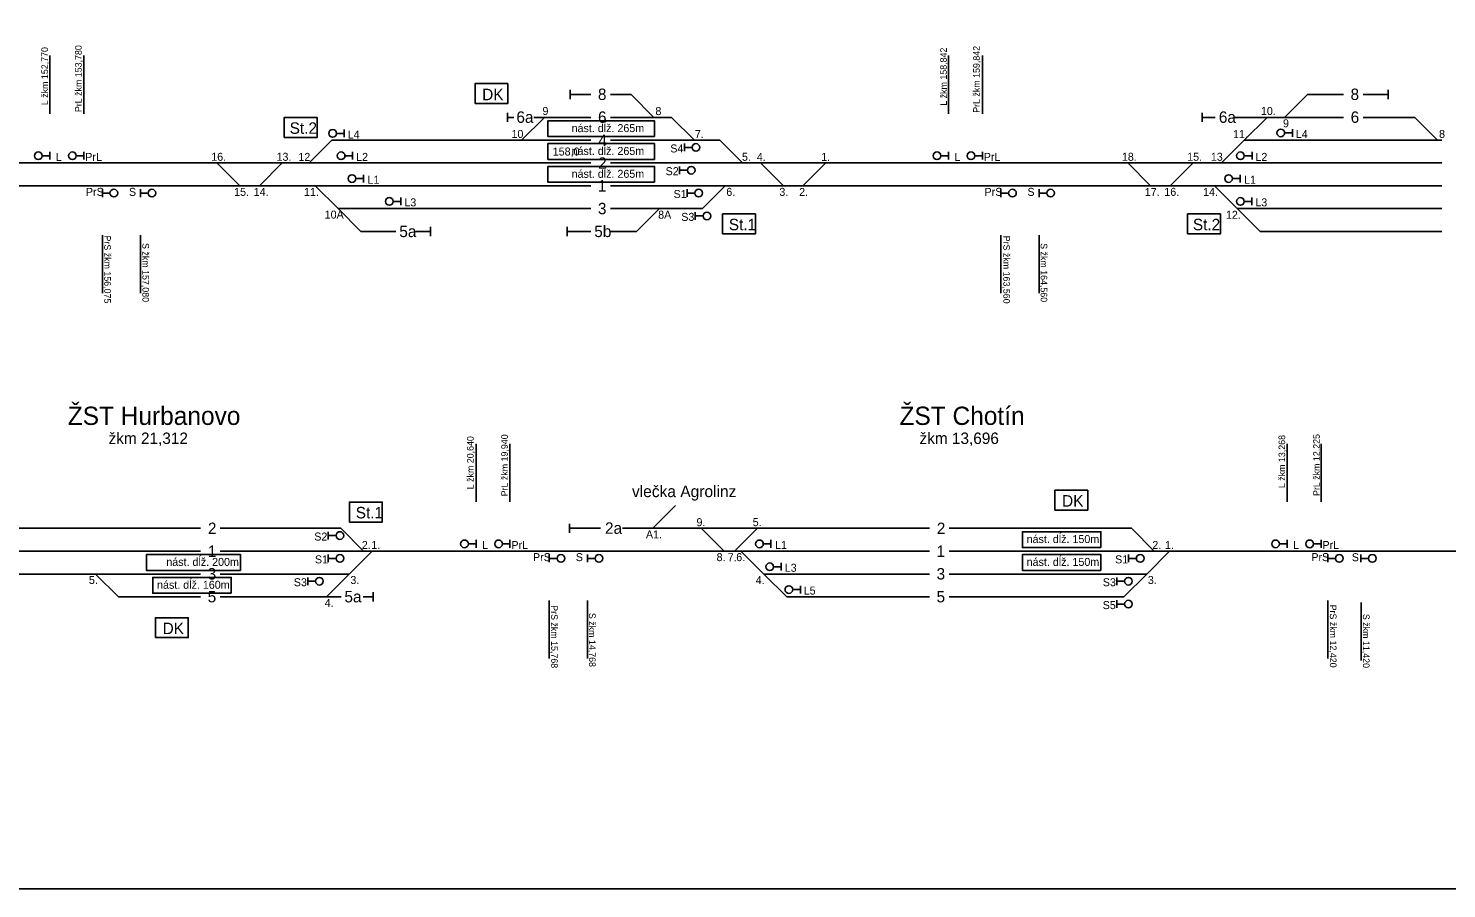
# Model space of a CAD drawing. Extents: x -119 to 851, y -238 to 59.
# Drawn here: x 119.9 to 243.9, y -238 to -162.7 of the extents above; entities that cross this region are included whole.
import ezdxf

# ---------------------------------------------------------------- set-up
doc = ezdxf.new("R2010")
doc.units = 0
for name, color, linetype in [('budova', 7, 'Continuous'), ('Level 2', 7, 'Continuous'), ('nastupistia', 7, 'Continuous'), ('netlač', 7, 'Continuous'), ('popisky navestidla', 7, 'Continuous'), ('popisky stanic a zastavok', 7, 'Continuous'), ('PU_navestidla', 7, 'Continuous'), ('PU_oznacenie navestidiel', 7, 'Continuous'), ('PU_stan_kolaje', 7, 'Continuous'), ('PU_vlecky', 7, 'Continuous'), ('schema_km1-0', 7, 'Continuous')]:
    doc.layers.add(name, color=color, linetype=linetype)

msp = doc.modelspace()

# ---------------------------------------------------------------- linework, layer by layer
at = {"layer": 'budova'}
for points in [[(158.96, -169.3), (161.82, -169.3), (161.82, -167.55), (158.96, -167.55)], [(142.27, -172.26), (145.14, -172.26), (145.14, -170.51), (142.27, -170.51)], [(180.61, -180.7), (183.48, -180.7), (183.48, -178.95), (180.61, -178.95)], [(221.27, -180.7), (224.14, -180.7), (224.14, -178.95), (221.27, -178.95)], [(209.67, -204.88), (212.54, -204.88), (212.54, -203.13), (209.67, -203.13)], [(147.97, -205.92), (150.84, -205.92), (150.84, -204.17), (147.97, -204.17)], [(131, -216.04), (133.87, -216.04), (133.87, -214.29), (131, -214.29)]]:
    msp.add_lwpolyline(points, close=True, dxfattribs=at)
at = {"layer": 'Level 2'}
for p, q in [((167.26, -168.9), (167.26, -168.1)), ((169.07, -168.5), (167.26, -168.5)), ((172.6, -168.5), (170.8, -168.5)), ((171.05, -168.5), (170.9, -168.5)), ((234.91, -168.5), (231.76, -168.5)), ((238.83, -168.5), (236.63, -168.5)), ((238.83, -168.9), (238.83, -168.1)), ((161.8, -170.9), (161.8, -170.1)), ((162.35, -170.5), (161.8, -170.5)), ((169.07, -170.5), (164.1, -170.5)), ((168.69, -170.5), (168.47, -170.5)), ((176.15, -170.5), (170.8, -170.5)), ((222.55, -170.9), (222.55, -170.1)), ((223.7, -170.5), (222.55, -170.5)), ((234.91, -170.5), (225.42, -170.5)), ((241.14, -170.5), (236.63, -170.5)), ((146.43, -172.49), (169.07, -172.49)), ((170.8, -172.49), (180.37, -172.49)), ((226.23, -172.49), (243.51, -172.49)), ((99.1, -174.49), (121.77, -174.49)), ((129.68, -174.49), (137.9, -174.49)), ((137.9, -174.49), (154.1, -174.49)), ((154.1, -174.49), (169.07, -174.49)), ((170.8, -174.49), (177.69, -174.49)), ((177.69, -174.49), (200.36, -174.49)), ((208.28, -174.49), (212.34, -174.49)), ((212.34, -174.49), (228.53, -174.49)), ((228.53, -174.49), (243.51, -174.49)), ((118.4, -176.49), (121.77, -176.49)), ((129.68, -176.49), (152.9, -176.49)), ((152.9, -176.49), (169.07, -176.49)), ((170.8, -176.49), (178.69, -176.49)), ((178.69, -176.49), (196.99, -176.49)), ((196.99, -176.49), (200.36, -176.49)), ((208.28, -176.49), (227.33, -176.49)), ((227.33, -176.49), (243.51, -176.49)), ((146.97, -178.49), (169.07, -178.49)), ((170.8, -178.49), (178.84, -178.49)), ((225.62, -178.49), (243.51, -178.49)), ((152.02, -180.49), (148.97, -180.49)), ((151.67, -180.49), (151.38, -180.49)), ((154.19, -180.49), (153.75, -180.49)), ((155.06, -180.49), (154.19, -180.49)), ((155.06, -180.89), (155.06, -180.09)), ((167, -180.89), (167, -180.09)), ((169.07, -180.49), (167, -180.49)), ((173.08, -180.49), (170.8, -180.49)), ((243.51, -180.49), (227.62, -180.49)), ((115.86, -206.47), (134.94, -206.47)), ((136.67, -206.47), (147.22, -206.47)), ((167.22, -206.87), (167.22, -206.07)), ((167.22, -206.47), (169.94, -206.47)), ((171.84, -206.47), (198.69, -206.47)), ((200.41, -206.47), (216.36, -206.47)), ((112.78, -208.47), (134.94, -208.47)), ((136.67, -208.47), (159.04, -208.47)), ((168.78, -208.47), (183.72, -208.47)), ((180.73, -208.47), (184.79, -208.47)), ((183.72, -208.47), (198.69, -208.47)), ((200.41, -208.47), (207.31, -208.47)), ((207.31, -208.47), (229.98, -208.47)), ((278.64, -208.47), (236.42, -208.47)), ((115.47, -210.47), (134.94, -210.47)), ((136.67, -210.47), (147.95, -210.47)), ((184.21, -210.47), (198.69, -210.47)), ((200.41, -210.47), (217.7, -210.47)), ((150.03, -212.86), (150.03, -212.07)), ((127.77, -212.46), (134.94, -212.46)), ((136.67, -212.46), (145.95, -212.46)), ((147.23, -212.46), (145.95, -212.46)), ((150.03, -212.46), (149.16, -212.46)), ((186.21, -212.46), (198.69, -212.46)), ((200.41, -212.46), (215.7, -212.46))]:
    msp.add_line(p, q, dxfattribs=at)
at = {"layer": 'nastupistia'}
for points in [[(174.64, -172.18), (165.32, -172.18), (165.32, -170.8), (174.64, -170.8)], [(174.64, -174.18), (165.32, -174.18), (165.32, -172.8), (174.64, -172.8)], [(174.64, -176.18), (165.32, -176.18), (165.32, -174.8), (174.64, -174.8)], [(213.69, -208.15), (206.83, -208.15), (206.83, -206.77), (213.69, -206.77)], [(138.44, -210.15), (130.21, -210.15), (130.21, -208.77), (138.44, -208.77)], [(213.69, -210.15), (206.83, -210.15), (206.83, -208.77), (213.69, -208.77)], [(137.63, -212.15), (130.76, -212.15), (130.76, -210.77), (137.63, -210.77)]]:
    msp.add_lwpolyline(points, close=True, dxfattribs=at)
at = {"layer": 'netlač'}
for p, q in [((129.68, -174.49), (121.77, -174.49)), ((208.28, -174.49), (200.36, -174.49)), ((129.68, -176.49), (121.77, -176.49)), ((208.28, -176.49), (200.36, -176.49)), ((159.04, -208.47), (168.78, -208.47)), ((229.98, -208.47), (236.42, -208.47))]:
    msp.add_line(p, q, dxfattribs=at)
at = {"layer": 'popisky navestidla'}
for p, q in [((121.77, -170.18), (121.77, -165.09)), ((124.74, -170.18), (124.74, -165.09)), ((200.36, -170.18), (200.36, -165.09)), ((203.34, -170.18), (203.34, -165.09)), ((126.36, -180.81), (126.36, -185.9)), ((129.68, -180.81), (129.68, -185.9)), ((204.95, -180.81), (204.95, -185.9)), ((208.28, -180.81), (208.28, -185.9)), ((159.04, -204.15), (159.04, -199.06)), ((162.01, -204.15), (162.01, -199.06)), ((229.98, -204.15), (229.98, -199.06)), ((232.95, -204.15), (232.95, -199.06)), ((165.45, -212.78), (165.45, -217.87)), ((168.78, -212.78), (168.78, -217.87)), ((233.54, -212.78), (233.54, -217.87)), ((236.45, -218.04), (236.45, -212.95))]:
    msp.add_line(p, q, dxfattribs=at)
msp.add_lwpolyline([(-118.95, -238.01), (851.05, -238.01), (851.05, 58.99), (-118.95, 58.99)], close=True, dxfattribs=at)
at = {"layer": 'PU_navestidla'}
for p, q in [((147.51, -171.9), (146.84, -171.9)), ((147.51, -171.57), (147.51, -172.24)), ((230.44, -171.86), (229.77, -171.86)), ((230.44, -171.52), (230.44, -172.19)), ((121.77, -173.52), (121.77, -174.19)), ((124.74, -173.52), (124.74, -174.19)), ((148.24, -173.52), (148.24, -174.19)), ((177.26, -173.47), (177.26, -172.79)), ((177.26, -173.13), (177.93, -173.13)), ((200.36, -173.52), (200.36, -174.19)), ((203.34, -173.52), (203.34, -174.19)), ((226.91, -173.52), (226.91, -174.19)), ((121.77, -173.86), (121.1, -173.86)), ((124.74, -173.86), (124.07, -173.86)), ((148.24, -173.86), (147.57, -173.86)), ((176.85, -175.47), (176.85, -174.79)), ((200.36, -173.86), (199.69, -173.86)), ((203.34, -173.86), (202.67, -173.86)), ((226.91, -173.86), (226.24, -173.86)), ((149.2, -175.86), (148.53, -175.86)), ((149.2, -175.52), (149.2, -176.19)), ((176.85, -175.13), (177.52, -175.13)), ((225.87, -175.86), (225.2, -175.86)), ((225.87, -175.52), (225.87, -176.19)), ((126.36, -177.47), (126.36, -176.79)), ((126.36, -177.13), (127.03, -177.13)), ((129.68, -177.47), (129.68, -176.79)), ((129.68, -177.13), (130.36, -177.13)), ((177.5, -177.46), (177.5, -176.79)), ((177.5, -177.13), (178.17, -177.13)), ((204.95, -177.47), (204.95, -176.79)), ((204.95, -177.13), (205.62, -177.13)), ((208.28, -177.47), (208.28, -176.79)), ((208.28, -177.13), (208.95, -177.13)), ((152.47, -177.86), (151.8, -177.86)), ((152.47, -177.52), (152.47, -178.19)), ((226.9, -177.86), (226.23, -177.86)), ((226.9, -177.52), (226.9, -178.19)), ((178.22, -179.46), (178.22, -178.79)), ((178.22, -179.13), (178.9, -179.13)), ((146.12, -207.44), (146.12, -206.77)), ((146.12, -207.1), (146.8, -207.1)), ((159.04, -207.83), (158.37, -207.83)), ((159.04, -207.49), (159.04, -208.17)), ((162.01, -207.83), (161.34, -207.83)), ((162.01, -207.49), (162.01, -208.17)), ((184.83, -207.83), (184.16, -207.83)), ((184.83, -207.49), (184.83, -208.17)), ((229.98, -207.83), (229.31, -207.83)), ((229.98, -207.49), (229.98, -208.17)), ((232.95, -207.83), (232.28, -207.83)), ((232.95, -207.49), (232.95, -208.17)), ((146.12, -209.44), (146.12, -208.77)), ((146.12, -209.1), (146.8, -209.1)), ((165.45, -209.44), (165.45, -208.77)), ((165.45, -209.1), (166.13, -209.1)), ((168.78, -209.44), (168.78, -208.77)), ((168.78, -209.1), (169.45, -209.1)), ((185.74, -209.49), (185.74, -210.17)), ((216.12, -209.44), (216.12, -208.77)), ((216.12, -209.1), (216.79, -209.1)), ((233.54, -209.44), (233.54, -208.77)), ((233.54, -209.1), (234.21, -209.1)), ((236.42, -209.44), (236.42, -208.77)), ((236.42, -209.1), (237.09, -209.1)), ((144.33, -211.44), (144.33, -210.76)), ((185.74, -209.83), (185.07, -209.83)), ((215.09, -211.44), (215.09, -210.77)), ((144.33, -211.1), (145, -211.1)), ((187.41, -211.83), (186.73, -211.83)), ((187.41, -211.49), (187.41, -212.16)), ((215.09, -211.1), (215.76, -211.1)), ((215.09, -213.44), (215.09, -212.76)), ((215.09, -213.1), (215.76, -213.1))]:
    msp.add_line(p, q, dxfattribs=at)
for centre in [(146.5, -171.9), (229.43, -171.86), (120.76, -173.86), (123.74, -173.86), (147.24, -173.86), (178.27, -173.13), (199.36, -173.86), (202.33, -173.86), (225.9, -173.86), (177.86, -175.13), (148.19, -175.86), (224.86, -175.86), (127.36, -177.13), (130.69, -177.13), (178.51, -177.13), (205.96, -177.13), (209.29, -177.13), (151.46, -177.86), (225.9, -177.86), (179.23, -179.13), (147.13, -207.1), (158.03, -207.83), (161.01, -207.83), (183.83, -207.83), (228.97, -207.83), (231.95, -207.83), (147.13, -209.1), (166.46, -209.1), (169.79, -209.1), (184.73, -209.83), (217.13, -209.1), (234.54, -209.1), (237.43, -209.1), (145.34, -211.1), (216.1, -211.1), (186.4, -211.83), (216.1, -213.1)]:
    msp.add_circle(centre, 0.336, dxfattribs=at)
at = {"layer": 'PU_stan_kolaje'}
for points in [[(172.6, -168.5), (174.6, -170.5)], [(231.76, -168.5), (229.76, -170.5)], [(165.03, -170.5), (163.03, -172.49)], [(176.15, -170.5), (178.15, -172.49)], [(228.23, -170.5), (226.23, -172.49)], [(241.14, -170.5), (243.13, -172.49)], [(146.43, -172.49), (144.43, -174.49)], [(180.37, -172.49), (182.36, -174.49)], [(226.23, -172.49), (224.24, -174.49)], [(136.38, -174.49), (138.38, -176.49)], [(142.09, -174.49), (140.1, -176.49)], [(183.92, -174.49), (185.92, -176.49)], [(189.63, -174.49), (187.63, -176.49)], [(216.04, -174.49), (218.04, -176.49)], [(221.75, -174.49), (219.75, -176.49)], [(144.98, -176.49), (146.97, -178.49)], [(180.84, -176.49), (178.84, -178.49)], [(223.62, -176.49), (225.61, -178.49)], [(146.97, -178.49), (148.97, -180.49)], [(175.08, -178.49), (173.08, -180.49)], [(225.61, -178.49), (227.61, -180.49)], [(176.5, -204.47), (174.5, -206.47)], [(147.22, -206.47), (149.21, -208.47)], [(178.73, -206.47), (180.73, -208.47)], [(183.66, -206.47), (181.66, -208.47)], [(216.36, -206.47), (218.36, -208.47)], [(149.95, -208.47), (147.95, -210.47)], [(182.21, -208.47), (184.21, -210.47)], [(219.7, -208.47), (217.7, -210.47)], [(125.77, -210.47), (127.77, -212.46)], [(147.95, -210.47), (145.95, -212.46)], [(184.21, -210.47), (186.21, -212.46)], [(217.7, -210.47), (215.7, -212.46)]]:
    msp.add_lwpolyline(points, dxfattribs=at)

# ---------------------------------------------------------------- texts
at = {"layer": 'budova'}
for s, p in [('DK', (159.58, -169)), ('St.2', (142.74, -171.94)), ('St.1', (181.15, -180.38)), ('St.2', (221.74, -180.38)), ('St.1', (148.52, -205.6)), ('DK', (210.3, -204.57)), ('DK', (131.63, -215.73))]:
    msp.add_text(s, height=1.004, dxfattribs=at).set_placement(p)
at = {"layer": 'nastupistia'}
for s, p in [('nást. dĺž. 265m', (167.4, -171.79)), ('nást. dĺž. 265m', (167.4, -173.79)), ('nást. dĺž. 265m', (167.4, -175.79)), ('nást. dĺž. 150m', (207.2, -207.76)), ('nást. dĺž. 200m', (131.95, -209.76)), ('nást. dĺž. 150m', (207.2, -209.76)), ('nást. dĺž. 160m', (131.14, -211.76))]:
    msp.add_text(s, height=0.7, dxfattribs=at).set_placement(p)
at = {"layer": 'popisky navestidla'}
for s, rotation, p in [('L žkm 152,770', 90, (121.6, -169.43)), ('PrL žkm 153,780', 90, (124.55, -170.04)), ('L žkm 158,842', 90, (200.22, -169.48)), ('PrL žkm 159,842', 90, (203.1, -170.1)), ('PrS žkm 156,075', 270, (126.52, -180.84)), ('PrS žkm 163,560', 270, (205.16, -180.86)), ('S žkm 157,080', 270, (129.86, -181.5)), ('S žkm 164,560 ', 270, (208.42, -181.51)), ('L žkm 20,640', 90, (158.83, -203.05)), ('PrL žkm 19,940', 90, (161.82, -203.67)), ('L žkm 13,268', 90, (229.81, -202.95)), ('PrL žkm 12,225 ', 90, (232.84, -203.64)), ('PrS žkm 15,768', 270, (165.61, -213.2)), ('PrS žkm 12,420', 270, (233.72, -213.15)), ('S žkm 14,768', 270, (168.92, -213.87)), ('S žkm 11,420', 270, (236.61, -213.96))]:
    msp.add_text(s, height=0.5793, rotation=rotation, dxfattribs=at).set_placement(p)
at = {"layer": 'popisky stanic a zastavok'}
for s, height, p in [('ŽST Hurbanovo', 1.6, (123.33, -197.42)), ('ŽST Chotín', 1.6, (196.08, -197.42)), ('žkm 21,312', 1.004, (126.9, -199.09)), ('žkm 13,696', 1.004, (197.83, -199.09))]:
    msp.add_text(s, height=height, dxfattribs=at).set_placement(p)
at = {"layer": 'PU_oznacenie navestidiel'}
for s, p in [('9', (164.85, -170.29)), ('8', (174.73, -170.3)), ('10.', (227.69, -170.29)), ('9', (229.62, -171.37)), ('L4', (147.81, -172.35)), ('10', (162.14, -172.3)), ('7.', (178.18, -172.31)), ('11.', (225.25, -172.31)), ('L4', (230.74, -172.31)), ('8', (243.27, -172.3)), ('L', (122.29, -174.31)), ('PrL', (124.86, -174.31)), ('16.', (135.88, -174.3)), ('13.', (141.59, -174.3)), ('12.', (143.5, -174.31)), ('L2', (148.55, -174.31)), ('S4', (176.03, -173.57)), ('5.', (182.3, -174.3)), ('4.', (183.6, -174.31)), ('1.', (189.23, -174.31)), ('L', (200.88, -174.31)), ('PrL', (203.45, -174.31)), ('18.', (215.53, -174.3)), ('15.', (221.24, -174.3)), ('13.', (223.31, -174.3)), ('L2', (227.21, -174.31)), ('S2', (175.62, -175.56)), ('L1', (149.55, -176.31)), ('L1', (226.22, -176.31)), ('PrS', (124.92, -177.37)), ('S', (128.68, -177.37)), ('15.', (137.88, -177.37)), ('14.', (139.59, -177.38)), ('11.', (143.99, -177.38)), ('S1', (176.32, -177.56)), ('6.', (180.93, -177.37)), ('3.', (185.57, -177.37)), ('2.', (187.3, -177.38)), ('PrS', (203.52, -177.37)), ('S', (207.27, -177.37)), ('17.', (217.53, -177.38)), ('16.', (219.24, -177.37)), ('14.', (222.63, -177.38)), ('L3', (152.77, -178.29)), ('L3', (227.2, -178.29)), ('10A', (145.8, -179.36)), ('8A', (174.97, -179.37)), ('S3', (176.99, -179.56)), ('12.', (224.63, -179.38)), ('9.', (178.32, -206.28)), ('5.', (183.24, -206.28)), ('S2', (144.89, -207.54)), ('A1.', (173.9, -207.35)), ('2.', (149.05, -208.28)), ('1.', (149.88, -208.28)), ('L', (159.56, -208.28)), ('PrL', (162.13, -208.28)), ('L1', (185.19, -208.28)), ('2.', (218.19, -208.28)), ('1.', (219.3, -208.28)), ('L', (230.5, -208.28)), ('PrL', (233.07, -208.28)), ('S1', (144.95, -209.54)), ('PrS', (164.02, -209.34)), ('S', (167.77, -209.34)), ('8.', (180.08, -209.34)), ('7.', (181.05, -209.35)), ('6.', (181.8, -209.34)), ('L3', (186.04, -210.27)), ('S1', (214.94, -209.54)), ('PrS', (232.1, -209.34)), ('S', (235.64, -209.35)), ('5.', (125.18, -211.34)), ('S3', (143.1, -211.54)), ('3.', (148.05, -211.34)), ('4.', (183.5, -211.35)), ('S3', (213.86, -211.54)), ('3.', (217.8, -211.34)), ('L5', (187.7, -212.27)), ('4.', (145.8, -213.35)), ('S5', (213.85, -213.54))]:
    msp.add_text(s, height=0.7, dxfattribs=at).set_placement(p)
at = {"layer": 'PU_stan_kolaje'}
for s, height, p in [('8', 1, (169.7, -168.98)), ('8', 1, (235.53, -168.98)), ('6a', 1.004, (162.57, -170.98)), ('6', 1, (169.71, -170.98)), ('6a', 1.004, (224.01, -170.98)), ('6', 1, (235.54, -170.98)), ('4', 1, (169.74, -173)), ('2', 1, (169.72, -175)), ('1', 1, (169.7, -176.99)), ('3', 1, (169.7, -178.98)), ('5a', 1.004, (152.33, -180.98)), ('5b', 1.004, (169.38, -180.98)), ('2', 1, (135.59, -206.97)), ('2a', 1.004, (170.32, -206.95)), ('2', 1, (199.34, -206.97)), ('1', 1, (135.58, -208.97)), ('1', 1, (199.32, -208.97)), ('3', 1, (135.57, -210.95)), ('3', 1, (199.32, -210.95)), ('5', 1, (135.57, -212.95)), ('5a', 1.004, (147.53, -212.95)), ('5', 1, (199.32, -212.95))]:
    msp.add_text(s, height=height, dxfattribs=at).set_placement(p)
at = {"layer": 'PU_vlecky'}
msp.add_text('vlečka Agrolinz', height=1.015, dxfattribs=at).set_placement((172.68, -203.74))
at = {"layer": 'schema_km1-0'}
msp.add_text('158,0', height=0.7, dxfattribs=at).set_placement((165.75, -173.84))

doc.saveas('drawing.dxf')
